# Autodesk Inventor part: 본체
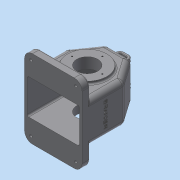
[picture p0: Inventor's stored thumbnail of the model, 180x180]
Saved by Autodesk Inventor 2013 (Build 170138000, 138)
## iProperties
Created: 2016-12
Part Number: 본체
Material: 일반
Document SubType Name: Modeling
Designer: dgall
Density: 1 g/cm^3
Author: dgall
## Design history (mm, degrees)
sketch "스케치1"
  geometry: L1 (-55, -65)-(55, -65); L2 (55, -65)-(55, 15); L3 (55, 15)-(23.491, 60); L4 (23.491, 60)-(-23.491, 60); L5 (-23.491, 60)-(-55, 15); L6 (-55, 15)-(-55, -65); 2 further points
  constraints: 12 end point, 1 horizontal, 1 horizontal alignment, 1 midpoint, 1 parallel, 1 perpendicular, 1 vertical, 1 vertical alignment
  dimensions: "d0" = 35 deg angle of L6 L5; "d1" = 35 deg angle of L2 L3; "d2" = 80 distance from line of L2.end L1; "d4" = 125 distance between parallel lines of L1 L4; "d5" = 110 distance of L1.start L1.end; "d6" = 65 distance from line of L1 point (0, 0)
extrude "돌출1" new body sketch "스케치1" distance "d7" = 5; taper "d8" = 0 deg
sketch "스케치2"
  geometry: L1 (-55, -65)-(55, -65) reference; L2 (55, -65)-(55, 15) reference; L3 (55, 15)-(23.491, 60) reference; L4 (23.491, 60)-(-23.491, 60) reference; L5 (-23.491, 60)-(-55, 15) reference; L6 (-55, 15)-(-55, -65) reference; L7 (-55, -65)-(55, -65) reference; L8 (55, -65)-(55, 15) reference; L9 (55, 15)-(23.491, 60) reference; L10 (23.491, 60)-(-23.491, 60) reference; L11 (-23.491, 60)-(-55, 15) reference; L12 (-55, 15)-(-55, -65) reference; L13 (20.888, 55)-(50, 13.424); L14 (50, 13.424)-(50, -60); L15 (50, -60)-(-50, -60); L16 (-50, -60)-(-50, 13.424); L17 (-50, 13.424)-(-20.888, 55); L18 (-20.888, 55)-(20.888, 55); 1 further point
  constraints: 12 end point, 5 other
  dimensions: "d9" = 5 distance between parallel lines of L18 L4
extrude "돌출2" join sketch "스케치2" distance "d10" = 67; taper "d11" = 0 deg
sketch "스케치3"
  geometry: L1 (50, 13.424)-(50, -60) reference; L2 (50, -60)-(-50, -60) reference; L3 (-50, -60)-(-50, 13.424) reference; L4 (-50, 13.424)-(-20.888, 55) reference; L5 (-20.888, 55)-(20.888, 55) reference; L6 (20.888, 55)-(50, 13.424) reference; L7 (-55, -65)-(55, -65) reference; L8 (55, -65)-(55, 15) reference; L9 (55, 15)-(23.491, 60) reference; L10 (23.491, 60)-(-23.491, 60) reference; L11 (-23.491, 60)-(-55, 15) reference; L12 (-55, 15)-(-55, -65) reference; 1 further point
extrude "돌출3" join sketch "스케치3" distance "d12" = 5; taper "d13" = 0 deg
sketch "스케치4"
  geometry: L1 (50, -60)-(-50, -60) reference; L2 (-50, -60)-(-50, 13.424) reference; L3 (-50, 13.424)-(-20.888, 55) reference; L4 (-20.888, 55)-(20.888, 55) reference; L5 (20.888, 55)-(50, 13.424) reference; L6 (50, 13.424)-(50, -60) reference; L7 (-55, -65)-(55, -65) reference; L8 (55, -65)-(55, 15) reference; L9 (55, 15)-(23.491, 60) reference; L10 (23.491, 60)-(-23.491, 60) reference; L11 (-23.491, 60)-(-55, 15) reference; L12 (-55, 15)-(-55, -65) reference; L13 (-20.888, 55)-(20.888, 55); L14 (20.888, 55)-(50, 13.424); L15 (50, 13.424)-(50, -60); L16 (50, -60)-(-50, -60); L17 (-50, -60)-(-50, 13.424); L18 (-50, 13.424)-(-20.888, 55); 1 further point
  constraints: 12 end point, 5 other
  dimensions: "d14" = 5 distance between parallel lines of L13 L10
extrude "돌출4" join sketch "스케치4" distance "d15" = 5; taper "d16" = 0 deg
sketch "스케치5"
  geometry: L1 (0, 0)-(110, 0) reference; L2 (110, 0)-(110, 77) reference; L3 (0, 77)-(110, 77) reference; L4 (0, 0)-(0, 77) reference; L5 (105, 72)-(105, 5); L6 (105, 5)-(5, 5); L7 (5, 5)-(5, 72); L8 (5, 72)-(105, 72); 1 further point
  constraints: 8 end point, 3 other
  dimensions: "d17" = 5 distance between parallel lines of L8 L3
extrude "돌출5" cut sketch "스케치5" distance "d18" = 10; taper "d19" = 0 deg
sketch "스케치6"
  geometry: L1 (0, 0)-(110, 0) reference; L2 (110, 0)-(110, 77) reference; L3 (0, 77)-(110, 77) reference; L4 (0, 0)-(0, 77) reference; L5 (0, 113.5)-(110, 113.5); L6 (110, 113.5)-(110, -36.5); L7 (110, -36.5)-(0, -36.5); L8 (0, -36.5)-(0, 113.5); 5 further points
  constraints: 8 end point, 4 midpoint, 2 parallel, 1 coincident, 1 horizontal, 1 perpendicular, 1 vertical alignment
  dimensions: "d20" = 110 distance of L5.start L5.end; "d23" = 150 distance of L5.end L6.end
extrude "돌출6" join sketch "스케치6" distance "d24" = 15; taper "d25" = 0 deg
fillet "모깎기1" dims "d26" = 15
sketch "스케치7"
  geometry: L1 (0, -10)-(0, 82); L2 (0, 82)-(37.5, 82); L3 (60, 77)-(15, 77) reference; L4 (15, 77)-(-50, 77) reference; L5 (13.424, 72)-(-65, 72) reference; L6 (55, 72)-(13.424, 72) reference; L7 (55, 5)-(13.424, 5) reference; L8 (-65, 5)-(13.424, 5) reference; L9 (15, 0)-(-50, 0) reference; L10 (60, 0)-(15, 0) reference; L11 (37.5, 82)-(37.5, 77); L12 (37.5, 72)-(27, 61.5); L13 (27, 61.5)-(0, 61.5); L14 (37.5, 72)-(37.5, 77); L15 (31, 0)-(31, -10); L16 (31, -10)-(0, -10); L17 (31, 0)-(0, 0)
  constraints: 18 end point, 5 perpendicular, 4 point on line, 2 coincident, 1 collinear, 1 midpoint, 1 parallel, 1 vertical, 1 vertical alignment
  dimensions: "d27" = 75 diameter of L11 L1; "d30" = 54 diameter of L12.end L1; "d31" = 45 deg angle of L13 L12; "d32" = 5 distance between parallel lines of L2 L3; "d33" = 62 diameter of L15 L1; "d34" = 10 distance between parallel lines of L16 L9
revolve "회전1" sketch "스케치7" stored, may be unused: angle "d35" = 90 deg
sketch "스케치8"
  geometry: C1 r 31 at (0, 0); 1 further point
  constraints: 1 centre point, 1 coincident
  dimensions: "d36" = 62 diameter of C1
extrude "돌출7" join sketch "스케치8" distance "d38" = 10; taper "d39" = 0 deg
sketch "스케치9"
  geometry: C1 r 31 at (0, 0) reference; C2 r 20 at (0, 0)
  constraints: 1 centre point, 1 coincident
  dimensions: "d40" = 40 diameter of C2
extrude "돌출8" cut sketch "스케치9" distance "d42" = 15; taper "d43" = 0 deg
sketch "스케치10"
  geometry: C1 r 37.5 at (0, 0) reference; C2 r 20 at (0, 0)
  constraints: 1 centre point, 1 coincident
  dimensions: "d44" = 40 diameter of C2
extrude "돌출9" cut sketch "스케치10" distance "d46" = 24; taper "d47" = 0 deg
sketch "스케치11"
  geometry: C1 r 20 at (0, 0) reference; 1 further point
  constraints: 1 vertical alignment
  dimensions: "d48" = 26 distance of C1.centre point (0, 26)
hole "구멍1" sketch "스케치11" at (0, 26) diameter "d49" = 2.459; stored, may be unused: countersink angle "d53" = 90 deg, drill point angle "d55" = 118 deg; dims "d50" = 6, "d51" = 4, "d52" = 2, "d54" = 8
sketch "스케치12"
  geometry: C1 r 20 at (0, 0) reference; 1 further point
  constraints: 1 vertical alignment
  dimensions: "d59" = 29 distance of C1.centre point (0, 29)
hole "구멍2" sketch "스케치12" at (0, 29) diameter "d60" = 2.459; stored, may be unused: countersink angle "d64" = 90 deg, drill point angle "d66" = 118 deg; dims "d61" = 6, "d62" = 4, "d63" = 2, "d65" = 8
fillet "모깎기3" dims "d71" = 3
node "작업 평면1"
node "작업 평면2"
sketch "스케치13"
  geometry: L1 (-12, 15)-(-92, 15) reference; L2 (3, -120)-(3, 0) reference; L3 (-92, -135)-(-12, -135) reference; L4 (-107, -120)-(-107, 0) reference; L5 (-2, -26.5)-(-102, -26.5) reference; L6 (-102, -26.5)-(-102, -93.5) reference; L7 (-102, -93.5)-(-2, -93.5) reference; L8 (-2, -93.5)-(-2, -26.5) reference; A1 r 15 centre (-92, 0) between (-92, 15) and (-107, 0) reference; A2 r 15 centre (-12, 0) between (3, 0) and (-12, 15) reference; A3 r 15 centre (-12, -120) between (-12, -135) and (3, -120) reference; A4 r 15 centre (-92, -120) between (-107, -120) and (-92, -135) reference; 5 further points
  constraints: 2 horizontal alignment, 2 vertical alignment
  dimensions: "d74" = 12 distance from line of L4 point (-95, -123); "d75" = 12 distance from line of L3 point (-95, -123); "d76" = 12 distance from line of L1 point (-9, 3); "d77" = 12 distance from line of point (-9, 3) L2
hole "구멍3" sketch "스케치13" at (-95, -123), (-9, -123), (-9, 3), (-95, 3) diameter "d78" = 5; stored, may be unused: countersink angle "d82" = 90 deg, drill point angle "d84" = 0 deg; dims "d79" = 6, "d80" = 12, "d81" = 5, "d83" = 8
node "작업 평면4"
  node "작업 평면3"
sketch "스케치14"
  geometry: L1 (-19.326, 60)-(19.326, 60) reference; L2 (-12.5, 60)-(-12.5, 75); L3 (-12.5, 75)-(12.5, 75); L4 (12.5, 75)-(12.5, 60); L5 (-7.5, 60)-(-7.5, 70); L6 (-7.5, 70)-(7.5, 70); L7 (7.5, 70)-(7.5, 60); 3 further points
  constraints: 12 end point, 5 perpendicular, 4 point on line, 2 midpoint, 1 parallel, 1 vertical alignment
  dimensions: "d88" = 25 distance of L2.end L3.end; "d90" = 15 distance of L5.end L6.end; "d91" = 15 distance from line of L7.end L3; "d92" = 5 distance between parallel lines of L6 L3; "d93" = 5 distance between parallel lines of L4 L7
extrude "돌출10" join sketch "스케치14" distance "d94" = 8; taper "d95" = 0 deg
fillet "모깎기7" dims "d96" = 8
fillet "모깎기8" dims "d97" = 3
fillet "모깎기9" dims "d98" = 1
fillet "모깎기10" dims "d99" = 3
fillet "모깎기11" dims "d100" = 10
fillet "모깎기12" dims "d101" = 3
fillet "모깎기13" dims "d102" = 10
fillet "모깎기14" dims "d103" = 3
sketch "스케치15"
  geometry: L1 (120, 0)-(0, 0) reference; L2 (31.5, 76.847)-(88.5, 76.847) reference; 3 further points
  constraints: 1 midpoint, 1 vertical alignment, 1 other
  dimensions: "d104" = 45 distance from line of L1 point (60, 45)
extrude "돌출11" join sketch "스케치15" distance "d105" = 0.5; taper "d106" = 0 deg
node "솔리드1"
pattern_circular "원형 패턴1" dims angle "d57" = 360 deg
pattern_circular "원형 패턴2" dims angle "d68" = 360 deg
mirror "대칭1"
node "투영된 루프1"
node "투영된 루프2"
other parameters: "d86" = 38.5, "d87" = 18
